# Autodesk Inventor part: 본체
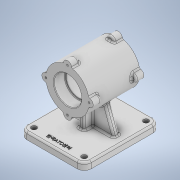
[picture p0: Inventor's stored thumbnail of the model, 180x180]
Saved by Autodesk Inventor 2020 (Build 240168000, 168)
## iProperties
Created: 2022-11
Part Number: 본체
Material: 일반
Document SubType Name: Modeling
Designer: owner
Density: 1 g/cm^3
Appearance: 기본값
Mass: 450.176 g
Surface Area: 800.088 cm^2
Volume: 450.176 cm^3
Author: owner
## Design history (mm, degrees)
sketch "스케치1"
  geometry: C1 r 37 at (0, 0); 1 further point
  constraints: 1 centre point, 1 coincident
  dimensions: "d0" = 74 diameter of C1
extrude "돌출1" new body sketch "스케치1" distance "d1" = 87; taper "d2" = 0 deg
sketch "스케치2"
  geometry: C1 r 23.5 at (0, 0); 1 further point
  constraints: 1 centre point, 1 coincident
  dimensions: "d3" = 47 diameter of C1
extrude "돌출2" cut sketch "스케치2" distance "d4" = 19; taper "d5" = 0 deg
sketch "스케치3"
  geometry: C1 r 23.5 at (0, 0); 1 further point
  constraints: 1 centre point, 1 coincident
  dimensions: "d6" = 47 diameter of C1
extrude "돌출3" cut sketch "스케치3" distance "d7" = 19; taper "d8" = 0 deg
sketch "스케치4"
  geometry: C1 r 21 at (0, 0); 1 further point
  constraints: 1 centre point, 1 coincident
  dimensions: "d9" = 42 diameter of C1
extrude "돌출4" cut sketch "스케치4" stored distance "d10" = 19; taper "d11" = 0 deg
sketch "스케치5"
  geometry: C1 r 37 at (0, 0) reference; C2 r 7 at (0, 37); 3 further points
  constraints: 1 centre point, 1 vertical alignment
  dimensions: "d12" = 14 diameter of C2; "d13" = 37 distance of point (0, 0) C2.centre
extrude "돌출5" join sketch "스케치5" distance "d14" = 14; taper "d15" = 0 deg
sketch "스케치6"
  geometry: A1 r 7 centre (0, 37) between (6.969, 36.338) and (-6.969, 36.338) reference; 2 further points
  constraints: 1 coincident
hole "구멍1" sketch "스케치6" at (0, 37) diameter "d16" = 3.242; stored, may be unused: countersink angle "d20" = 90 deg, drill point angle "d22" = 118 deg; dims "d17" = 8, "d18" = 4, "d19" = 2, "d21" = 10
sketch "스케치7"
  geometry: A1 r 7 centre (37, 0) between (36.338, -6.969) and (36.338, 6.969) reference; A2 r 37 centre (0, 0) between (36.338, -6.969) and (36.338, 6.969) reference; 1 further point
extrude "돌출6" join sketch "스케치7" distance "d26" = 14; taper "d27" = 0 deg
sketch "스케치8"
  geometry: A1 r 7 centre (37, 0) between (36.338, -6.969) and (36.338, 6.969) reference; 2 further points
  constraints: 1 coincident
hole "구멍2" sketch "스케치8" at (37, 0) diameter "d28" = 3.242; stored, may be unused: countersink angle "d32" = 90 deg, drill point angle "d34" = 118 deg; dims "d29" = 8, "d30" = 4, "d31" = 2, "d33" = 10
node "작업 평면2"
sketch "스케치9"
  geometry: L1 (55, 26.5)-(-55, 26.5); L2 (-55, 26.5)-(-55, -103.5); L3 (-55, -103.5)-(55, -103.5); L4 (55, -103.5)-(55, 26.5); 2 further points
  constraints: 8 end point, 2 parallel, 1 horizontal, 1 perpendicular, 1 vertical alignment
  dimensions: "d39" = 110 distance of L3.end L2.end; "d40" = 130 distance of L2.end L1.end; "d41" = 43.5 distance of point (0, -43.5) point (0, 0); "d42" = 70 distance from line of point (0, -43.5) L1; "d43" = 55 distance from line of point (0, 0) L4
extrude "돌출7" join sketch "스케치9" distance "d44" = 12; taper "d45" = 0 deg
node "작업 평면4"
sketch "스케치10"
  geometry: L1 (55, -70)-(-55, -70) reference; L2 (-55, -70)-(55, -70) reference; L3 (-41, -70)-(-25.336, -26.964); L4 (25.336, -26.964)-(41, -70); A1 r 37 centre (0, 0) between (-36.338, -6.969) and (-6.969, -36.338) reference; A2 r 37 centre (0, 0) between (6.969, -36.338) and (36.338, -6.969) reference; A3 r 37 centre (0, 0) between (-6.969, -36.338) and (6.969, -36.338) reference; A4 r 37 centre (0, 0) between (-36.338, -6.969) and (-6.969, -36.338) reference; A5 r 37 centre (0, 0) between (6.969, -36.338) and (36.338, -6.969) reference; 5 further points
  constraints: 4 end point, 2 point on circle, 2 point on line
  dimensions: "d47" = 110 deg angle of L3 L1; "d48" = 110 deg angle of L1 L4; "d49" = 14 distance of L3.start L1.end; "d50" = 14 distance of L1.start L4.end
extrude "돌출8" join sketch "스케치10" stored distance "d51" = 10; taper "d52" = 0 deg
sketch "스케치11"
  geometry: L1 (-37, -14)-(-37, -73) reference; L2 (-37, -23.5)-(-70, -23.5); L3 (-26.964, -38.5)-(-70, -38.5) reference; 1 further point
  constraints: 2 end point, 1 horizontal, 1 point on line
  dimensions: "d53" = 15 distance between parallel lines of L3 L2
feature "리브1" sketch "스케치11" dims "d54" = 1, "d55" = 10, "d56" = 0, "d57" = 0, "d58" = 1, "d59" = 1
sketch "스케치12"
  geometry: L1 (-37, -14)-(-37, -73) reference; L2 (-37, -63.5)-(-70.015, -63.5); L3 (-70, -48.5)-(-26.964, -48.5) reference; 1 further point
  constraints: 2 end point, 1 perpendicular, 1 point on line
  dimensions: "d60" = 15 distance between parallel lines of L2 L3
feature "리브2" sketch "스케치12" dims "d61" = 1, "d62" = 10, "d63" = 0, "d64" = 0, "d65" = 1, "d66" = 1
fillet "모깎기1" dims "d67" = 12
sketch "스케치13"
  geometry: L1 (-43, -26.5)-(43, -26.5) reference; L2 (55, -14.5)-(55, 91.5) reference; L3 (-55, 91.5)-(-55, -14.5) reference; L4 (43, 103.5)-(-43, 103.5) reference; 5 further points
  dimensions: "d71" = 12 distance from line of point (43, -14.5) L1; "d72" = 12 distance from line of L2 point (43, -14.5); "d73" = 12 distance from line of point (-43, -14.5) L1; "d74" = 12 distance from line of point (-43, -14.5) L3; "d75" = 12 distance from line of point (-43, 91.5) L3; "d76" = 12 distance from line of point (-43, 91.5) L4; "d77" = 12 distance from line of L2 point (43, 91.5); "d78" = 12 distance from line of point (43, 91.5) L4
hole "구멍3" sketch "스케치13" at (43, -14.5), (43, 91.5), (-43, 91.5), (-43, -14.5) diameter "d79" = 9; stored, may be unused: countersink angle "d83" = 90 deg, drill point angle "d85" = 0 deg; dims "d80" = 8, "d81" = 4, "d82" = 2, "d84" = 12
sketch "스케치14"
  geometry: L1 (-43, -26.5)-(43, -26.5) reference; L2 (-7, 0)-(7, 0) reference; 5 further points
  constraints: 1 midpoint, 1 vertical alignment, 1 other
  dimensions: "d86" = 12 distance from line of L1 point (0, -14.5)
feature "엠보싱1" sketch "스케치14" dims "d1" = 87, "d87" = 0.5, "d88" = 0
fillet "모깎기2" dims "d89" = 1
fillet "모깎기3" dims "d90" = 3
fillet "모깎기4" dims "d91" = 3
fillet "모깎기5" dims "d92" = 3
fillet "모깎기6" dims "d93" = 3
fillet "모깎기7" dims "d94" = 3
chamfer "모따기1" distance "d95" = 1; stored, may be unused: second distance "d96" = 2, angle "d97" = 45 deg
node "솔리드1"
pattern_circular "원형 패턴1" dims angle "d24" = 360 deg
pattern_circular "원형 패턴2" dims angle "d36" = 360 deg
feature "A9D066F2-1C7D-4E18-AEED-F7BC21143FA4" dims "d16" = 3.242, "d17" = 8, "d18" = 4, "d19" = 2, "d20" = 90 deg, "d21" = 10, "d22" = 118 deg
other parameters: "d38" = -82, "d46" = -43.5
